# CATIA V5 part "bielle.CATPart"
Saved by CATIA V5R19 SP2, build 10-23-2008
Part number: bielle
Bounding box of the stored display mesh (mm): x 0 to 50, y -39.613 to 1460.88, z -39.613 to 39.613
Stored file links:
  C:\Users\matthieu\Desktop\IAO\modele_CAO\bielle.CATPart
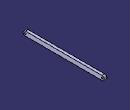
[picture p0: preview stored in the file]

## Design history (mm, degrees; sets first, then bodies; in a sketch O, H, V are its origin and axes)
Body1 (main body)
  Sketch1 on yz-plane, origin (0, 0, 0), H (0, 1, 0), V (0, 0, 1)
    construction line L1 (0, 0) -> (1421.267, 0)
    line L2 (0, 39.613) -> (1421.267, 39.613)
    line L3 (1421.267, -39.613) -> (0, -39.613)
    arc A1 centre (1421.267, 0) radius 39.613 from (1421.267, 39.613) to (1421.267, -39.613) cw
    arc A2 centre (0, 0) radius 39.613 from (0, -39.613) to (0, 39.613) cw
    circle A3 centre (0, 0) radius 15
    circle A4 centre (1421.267, 0) radius 15
    distance L1 L2 = 39.613
    radius A4 = 15
    radius A3 = 15
    length L2 = 1421.267
    horizontal: L1 H
    tangency: A1 L2, A2 L2, A1 L3, A2 L3
  Pad1: profile Sketch1, direction (1, 0, 0), length 50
